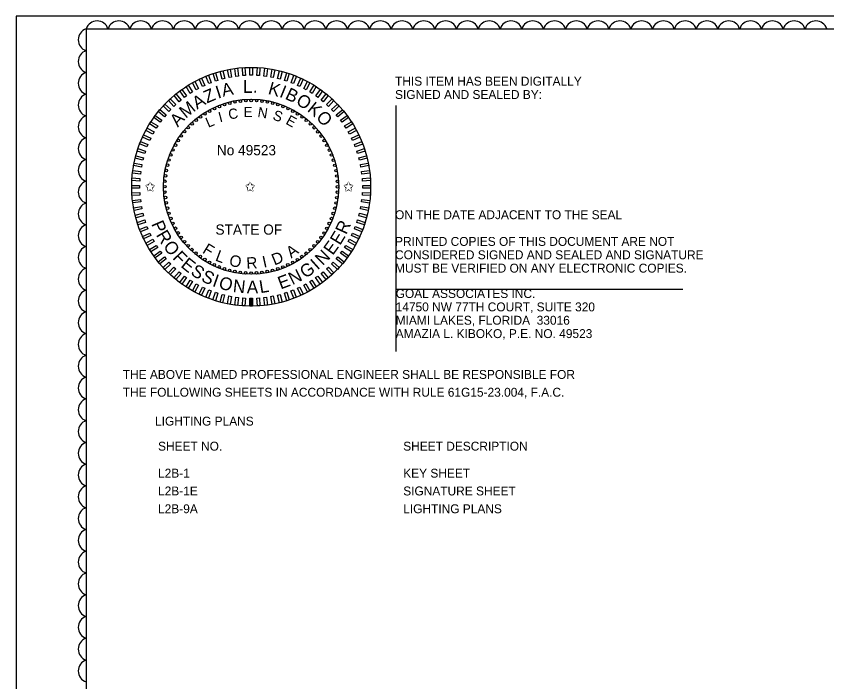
# Model space of a CAD drawing. Extents: x -816.9 to -790.1, y -2199.5 to -2188.9.
# Drawn here: x -811.34 to -804.97, y -2194.13 to -2188.9 of the extents above; entities that cross this region are included whole.
import ezdxf

# ---------------------------------------------------------------- set-up
doc = ezdxf.new("R2010")
doc.units = 0
for name, color, linetype in [('Cloud_dp', 7, 'Continuous'), ('Logo_dp', 7, 'Continuous'), ('NonPlottingEle_dp', 7, 'Continuous'), ('PlotBorder_dp', 7, 'Continuous'), ('ScratchEle_dp', 7, 'Continuous'), ('SheetBorder_dp', 7, 'Continuous'), ('TextMisc', 7, 'Continuous'), ('TextNotes', 7, 'Continuous')]:
    doc.layers.add(name, color=color, linetype=linetype)

msp = doc.modelspace()

# ---------------------------------------------------------------- linework, layer by layer
at = {"layer": 'Cloud_dp'}
for centre, start, end in [((-810.7002, -2189.0276), 17.5, 162.5), ((-810.5291, -2189.0276), 17.5, 162.5), ((-810.358, -2189.0276), 17.5, 162.5), ((-810.1868, -2189.0276), 17.5, 162.5), ((-810.0157, -2189.0276), 17.5, 162.5), ((-809.8446, -2189.0276), 17.5, 162.5), ((-809.6735, -2189.0276), 17.5, 162.5), ((-809.5024, -2189.0276), 17.5, 162.5), ((-809.3312, -2189.0276), 17.5, 162.5), ((-809.1601, -2189.0276), 17.5, 162.5), ((-808.989, -2189.0276), 17.5, 162.5), ((-808.8179, -2189.0276), 17.5, 162.5), ((-808.6467, -2189.0276), 17.5, 162.5), ((-808.4756, -2189.0276), 17.5, 162.5), ((-808.3045, -2189.0276), 17.5, 162.5), ((-808.1334, -2189.0276), 17.5, 162.5), ((-807.9622, -2189.0276), 17.5, 162.5), ((-807.7911, -2189.0276), 17.5, 162.5), ((-807.62, -2189.0276), 17.5, 162.5), ((-807.4489, -2189.0276), 17.5, 162.5), ((-807.2778, -2189.0276), 17.5, 162.5), ((-807.1066, -2189.0276), 17.5, 162.5), ((-806.9355, -2189.0276), 17.5, 162.5), ((-806.7644, -2189.0276), 17.5, 162.5), ((-806.5933, -2189.0276), 17.5, 162.5), ((-806.4221, -2189.0276), 17.5, 162.5), ((-806.251, -2189.0276), 17.5, 162.5), ((-806.0799, -2189.0276), 17.5, 162.5), ((-805.9088, -2189.0276), 17.5, 162.5), ((-805.7377, -2189.0276), 17.5, 162.5), ((-805.5665, -2189.0276), 17.5, 162.5), ((-805.3954, -2189.0276), 17.5, 162.5), ((-805.2243, -2189.0276), 17.5, 162.5), ((-805.0532, -2189.0276), 17.5, 162.5), ((-810.7588, -2189.0862), 107.5, 252.5), ((-810.7588, -2189.2573), 107.5, 252.5), ((-810.7588, -2189.4284), 107.5, 252.5), ((-810.7588, -2189.5996), 107.5, 252.5), ((-810.7588, -2189.7707), 107.5, 252.5), ((-810.7588, -2189.9418), 107.5, 252.5), ((-810.7588, -2190.1129), 107.5, 252.5), ((-810.7588, -2190.2841), 107.5, 252.5), ((-810.7588, -2190.4552), 107.5, 252.5), ((-810.7588, -2190.6263), 107.5, 252.5), ((-810.7588, -2190.7974), 107.5, 252.5), ((-810.7588, -2190.9685), 107.5, 252.5), ((-810.7588, -2191.1397), 107.5, 252.5), ((-810.7588, -2191.3108), 107.5, 252.5), ((-810.7588, -2191.4819), 107.5, 252.5), ((-810.7588, -2191.653), 107.5, 252.5), ((-810.7588, -2191.8242), 107.5, 252.5), ((-810.7588, -2191.9953), 107.5, 252.5), ((-810.7588, -2192.1664), 107.5, 252.5), ((-810.7588, -2192.3375), 107.5, 252.5), ((-810.7588, -2192.5087), 107.5, 252.5), ((-810.7588, -2192.6798), 107.5, 252.5), ((-810.7588, -2192.8509), 107.5, 252.5), ((-810.7588, -2193.022), 107.5, 252.5), ((-810.7588, -2193.1931), 107.5, 252.5), ((-810.7588, -2193.3643), 107.5, 252.5), ((-810.7588, -2193.5354), 107.5, 252.5), ((-810.7588, -2193.7065), 107.5, 252.5), ((-810.7588, -2193.8776), 107.5, 252.5), ((-810.7588, -2194.0488), 107.5, 252.5)]:
    msp.add_arc(centre, 0.0897, start, end, dxfattribs=at)
at = {"layer": 'Logo_dp'}
for p, q in [((-809.5, -2191.1804), (-809.5002, -2191.1179)), ((-809.49, -2191.1804), (-809.4902, -2191.1178)), ((-809.48, -2191.1804), (-809.4802, -2191.1178))]:
    msp.add_line(p, q, dxfattribs=at)
for points in [[(-809.5897, -2189.3711), (-809.6098, -2189.3737), (-809.6176, -2189.3116), (-809.5976, -2189.3091)], [(-809.5349, -2189.3666), (-809.555, -2189.3679), (-809.559, -2189.3055), (-809.5388, -2189.3042)], [(-809.4798, -2189.3655), (-809.5, -2189.3655), (-809.5, -2189.303), (-809.4798, -2189.303)], [(-809.4248, -2189.3679), (-809.445, -2189.3666), (-809.4411, -2189.3042), (-809.4209, -2189.3055)], [(-809.3701, -2189.3737), (-809.3901, -2189.3712), (-809.3823, -2189.3091), (-809.3623, -2189.3117)], [(-809.8031, -2189.4233), (-809.8219, -2189.4307), (-809.8449, -2189.3726), (-809.8261, -2189.3652)], [(-809.7511, -2189.4052), (-809.7703, -2189.4115), (-809.7896, -2189.352), (-809.7704, -2189.3458)], [(-809.698, -2189.3905), (-809.7176, -2189.3955), (-809.7332, -2189.335), (-809.7136, -2189.3299)], [(-809.6442, -2189.3791), (-809.664, -2189.3829), (-809.6758, -2189.3215), (-809.6559, -2189.3177)], [(-809.3158, -2189.3829), (-809.3357, -2189.3792), (-809.324, -2189.3177), (-809.3041, -2189.3215)], [(-809.2623, -2189.3956), (-809.2818, -2189.3905), (-809.2663, -2189.33), (-809.2467, -2189.335)], [(-809.2096, -2189.4115), (-809.2288, -2189.4053), (-809.2095, -2189.3458), (-809.1903, -2189.3521)], [(-809.158, -2189.4308), (-809.1768, -2189.4234), (-809.1538, -2189.3652), (-809.135, -2189.3727)], [(-809.9032, -2189.469), (-809.9209, -2189.4787), (-809.951, -2189.4239), (-809.9333, -2189.4142)], [(-809.8539, -2189.4446), (-809.8721, -2189.4532), (-809.8988, -2189.3966), (-809.8805, -2189.388)], [(-809.1077, -2189.4532), (-809.126, -2189.4446), (-809.0994, -2189.3881), (-809.0811, -2189.3967)], [(-809.059, -2189.4788), (-809.0767, -2189.4691), (-809.0466, -2189.4143), (-809.0289, -2189.424)], [(-809.9968, -2189.5268), (-810.0131, -2189.5387), (-810.0499, -2189.4881), (-810.0335, -2189.4763)], [(-809.9509, -2189.4964), (-809.968, -2189.5073), (-810.0015, -2189.4545), (-809.9844, -2189.4437)], [(-809.0119, -2189.5074), (-809.029, -2189.4965), (-808.9955, -2189.4438), (-808.9784, -2189.4546)], [(-808.9668, -2189.5388), (-808.9831, -2189.527), (-808.9464, -2189.4764), (-808.93, -2189.4883)], [(-810.0824, -2189.596), (-810.0971, -2189.6098), (-810.1399, -2189.5643), (-810.1252, -2189.5504)], [(-810.0407, -2189.5601), (-810.0562, -2189.573), (-810.0961, -2189.5248), (-810.0805, -2189.5119)], [(-808.9237, -2189.5731), (-808.9392, -2189.5602), (-808.8994, -2189.512), (-808.8838, -2189.5249)], [(-808.8828, -2189.61), (-808.8975, -2189.5961), (-808.8547, -2189.5505), (-808.84, -2189.5644)], [(-810.1217, -2189.6345), (-810.1356, -2189.6492), (-810.1812, -2189.6064), (-810.1673, -2189.5917)], [(-808.8443, -2189.6493), (-808.8582, -2189.6346), (-808.8126, -2189.5918), (-808.7988, -2189.6065)], [(-810.1929, -2189.7184), (-810.2048, -2189.7348), (-810.2553, -2189.698), (-810.2435, -2189.6817)], [(-810.1586, -2189.6753), (-810.1715, -2189.6909), (-810.2197, -2189.6511), (-810.2068, -2189.6355)], [(-808.8084, -2189.691), (-808.8213, -2189.6755), (-808.7731, -2189.6356), (-808.7602, -2189.6512)], [(-808.7752, -2189.7349), (-808.7871, -2189.7186), (-808.7365, -2189.6818), (-808.7246, -2189.6982)], [(-810.2243, -2189.7636), (-810.2352, -2189.7807), (-810.288, -2189.7472), (-810.2771, -2189.7301)], [(-808.7448, -2189.7808), (-808.7556, -2189.7638), (-808.7028, -2189.7303), (-808.692, -2189.7473)], [(-810.2529, -2189.8106), (-810.2626, -2189.8284), (-810.3174, -2189.7982), (-810.3077, -2189.7805)], [(-808.7173, -2189.8285), (-808.7271, -2189.8108), (-808.6723, -2189.7807), (-808.6625, -2189.7984)], [(-810.2785, -2189.8594), (-810.2871, -2189.8777), (-810.3436, -2189.8511), (-810.335, -2189.8328)], [(-808.6929, -2189.8779), (-808.7015, -2189.8596), (-808.6449, -2189.8329), (-808.6363, -2189.8512)], [(-810.3202, -2189.9612), (-810.3264, -2189.9805), (-810.3859, -2189.9611), (-810.3796, -2189.9419)], [(-810.3009, -2189.9097), (-810.3084, -2189.9285), (-810.3665, -2189.9054), (-810.359, -2189.8866)], [(-808.6716, -2189.9286), (-808.6791, -2189.9098), (-808.6209, -2189.8868), (-808.6135, -2189.9056)], [(-808.6536, -2189.9806), (-808.6598, -2189.9614), (-808.6004, -2189.9421), (-808.5941, -2189.9613)], [(-810.3361, -2190.0139), (-810.3412, -2190.0335), (-810.4017, -2190.0179), (-810.3967, -2189.9984)], [(-808.6388, -2190.0337), (-808.6439, -2190.0141), (-808.5833, -2189.9985), (-808.5783, -2190.0181)], [(-810.3488, -2190.0675), (-810.3526, -2190.0873), (-810.414, -2190.0756), (-810.4102, -2190.0558)], [(-808.6275, -2190.0875), (-808.6312, -2190.0677), (-808.5698, -2190.056), (-808.566, -2190.0758)], [(-810.358, -2190.1218), (-810.3605, -2190.1418), (-810.4226, -2190.134), (-810.42, -2190.1139)], [(-808.6195, -2190.142), (-808.622, -2190.1219), (-808.56, -2190.1141), (-808.5575, -2190.1342)], [(-810.3638, -2190.1765), (-810.3651, -2190.1967), (-810.4275, -2190.1927), (-810.4262, -2190.1726)], [(-808.6149, -2190.1968), (-808.6162, -2190.1767), (-808.5538, -2190.1727), (-808.5525, -2190.1929)], [(-810.3662, -2190.2315), (-810.3662, -2190.2517), (-810.4287, -2190.2517), (-810.4287, -2190.2315)], [(-808.6139, -2190.2519), (-808.6139, -2190.2317), (-808.5513, -2190.2317), (-808.5513, -2190.2519)], [(-810.3651, -2190.2865), (-810.3638, -2190.3067), (-810.4262, -2190.3106), (-810.4275, -2190.2904)], [(-808.6162, -2190.3069), (-808.615, -2190.2867), (-808.5526, -2190.2906), (-808.5538, -2190.3108)], [(-810.3606, -2190.3414), (-810.358, -2190.3614), (-810.4201, -2190.3693), (-810.4226, -2190.3492)], [(-808.622, -2190.3616), (-808.6195, -2190.3416), (-808.5575, -2190.3494), (-808.56, -2190.3695)], [(-810.3526, -2190.3958), (-810.3488, -2190.4157), (-810.4102, -2190.4274), (-810.414, -2190.4076)], [(-810.3412, -2190.4497), (-810.3362, -2190.4693), (-810.3967, -2190.4848), (-810.4018, -2190.4652)], [(-808.6439, -2190.4695), (-808.6389, -2190.4499), (-808.5783, -2190.4654), (-808.5834, -2190.485)], [(-808.6313, -2190.4159), (-808.6275, -2190.396), (-808.5661, -2190.4077), (-808.5699, -2190.4276)], [(-810.3265, -2190.5027), (-810.3202, -2190.522), (-810.3797, -2190.5413), (-810.3859, -2190.5221)], [(-808.6599, -2190.5221), (-808.6536, -2190.5029), (-808.5942, -2190.5222), (-808.6004, -2190.5415)], [(-810.3084, -2190.5547), (-810.301, -2190.5735), (-810.3591, -2190.5966), (-810.3666, -2190.5778)], [(-808.6791, -2190.5737), (-808.6717, -2190.5549), (-808.6136, -2190.5779), (-808.621, -2190.5967)], [(-810.2872, -2190.6055), (-810.2785, -2190.6238), (-810.3351, -2190.6504), (-810.3437, -2190.6321)], [(-808.7016, -2190.624), (-808.693, -2190.6057), (-808.6364, -2190.6323), (-808.645, -2190.6506)], [(-810.2627, -2190.6548), (-810.253, -2190.6726), (-810.3078, -2190.7027), (-810.3175, -2190.685)], [(-810.2353, -2190.7026), (-810.2244, -2190.7196), (-810.2772, -2190.7531), (-810.2881, -2190.7361)], [(-808.7557, -2190.7198), (-808.7449, -2190.7027), (-808.6921, -2190.7362), (-808.7029, -2190.7533)], [(-808.7271, -2190.6727), (-808.7174, -2190.655), (-808.6626, -2190.6851), (-808.6724, -2190.7028)], [(-810.2049, -2190.7484), (-810.193, -2190.7648), (-810.2436, -2190.8015), (-810.2554, -2190.7852)], [(-808.7872, -2190.7649), (-808.7753, -2190.7486), (-808.7247, -2190.7853), (-808.7366, -2190.8017)], [(-810.1716, -2190.7923), (-810.1587, -2190.8079), (-810.2069, -2190.8477), (-810.2198, -2190.8322)], [(-810.1357, -2190.834), (-810.1219, -2190.8488), (-810.1675, -2190.8916), (-810.1813, -2190.8768)], [(-808.8583, -2190.8489), (-808.8445, -2190.8342), (-808.7989, -2190.877), (-808.8127, -2190.8917)], [(-808.8214, -2190.808), (-808.8085, -2190.7925), (-808.7604, -2190.8323), (-808.7732, -2190.8479)], [(-810.0972, -2190.8734), (-810.0825, -2190.8872), (-810.1253, -2190.9328), (-810.14, -2190.919)], [(-808.8977, -2190.8874), (-808.8829, -2190.8735), (-808.8401, -2190.9191), (-808.8549, -2190.9329)], [(-810.0564, -2190.9103), (-810.0408, -2190.9232), (-810.0807, -2190.9713), (-810.0962, -2190.9585)], [(-810.0133, -2190.9445), (-809.9969, -2190.9564), (-810.0337, -2191.007), (-810.05, -2190.9951)], [(-808.9833, -2190.9565), (-808.9669, -2190.9446), (-808.9302, -2190.9952), (-808.9465, -2191.0071)], [(-808.9394, -2190.9233), (-808.9238, -2190.9104), (-808.884, -2190.9586), (-808.8995, -2190.9715)], [(-809.9681, -2190.976), (-809.951, -2190.9868), (-809.9845, -2191.0396), (-810.0016, -2191.0288)], [(-809.9211, -2191.0046), (-809.9034, -2191.0143), (-809.9335, -2191.0691), (-809.9512, -2191.0594)], [(-809.8723, -2191.0301), (-809.854, -2191.0387), (-809.8806, -2191.0953), (-809.8989, -2191.0867)], [(-809.1262, -2191.0388), (-809.1079, -2191.0302), (-809.0813, -2191.0868), (-809.0996, -2191.0954)], [(-809.0769, -2191.0144), (-809.0592, -2191.0047), (-809.029, -2191.0594), (-809.0467, -2191.0692)], [(-809.0292, -2190.9869), (-809.0121, -2190.9761), (-808.9786, -2191.0289), (-808.9957, -2191.0397)], [(-809.822, -2191.0526), (-809.8033, -2191.06), (-809.8263, -2191.1181), (-809.8451, -2191.1107)], [(-809.7705, -2191.0718), (-809.7513, -2191.0781), (-809.7706, -2191.1375), (-809.7898, -2191.1313)], [(-809.7178, -2191.0878), (-809.6982, -2191.0928), (-809.7138, -2191.1534), (-809.7333, -2191.1484)], [(-809.282, -2191.0929), (-809.2624, -2191.0878), (-809.2469, -2191.1484), (-809.2665, -2191.1534)], [(-809.229, -2191.0781), (-809.2097, -2191.0719), (-809.1904, -2191.1313), (-809.2097, -2191.1376)], [(-809.177, -2191.0601), (-809.1582, -2191.0526), (-809.1352, -2191.1108), (-809.154, -2191.1182)], [(-809.6642, -2191.1004), (-809.6444, -2191.1042), (-809.6561, -2191.1656), (-809.6759, -2191.1618)], [(-809.61, -2191.1097), (-809.5899, -2191.1122), (-809.5977, -2191.1742), (-809.6178, -2191.1717)], [(-809.5552, -2191.1155), (-809.535, -2191.1168), (-809.539, -2191.1792), (-809.5591, -2191.1779)], [(-809.5002, -2191.1179), (-809.48, -2191.1179), (-809.48, -2191.1804), (-809.5002, -2191.1804)], [(-809.4452, -2191.1168), (-809.425, -2191.1155), (-809.4211, -2191.1779), (-809.4413, -2191.1792)], [(-809.3903, -2191.1122), (-809.3703, -2191.1097), (-809.3624, -2191.1717), (-809.3825, -2191.1743)], [(-809.3359, -2191.1043), (-809.316, -2191.1005), (-809.3043, -2191.1619), (-809.3241, -2191.1657)]]:
    msp.add_lwpolyline(points, close=True, dxfattribs=at)
for centre in [(-809.6166, -2189.5752), (-809.5745, -2189.5686), (-809.5321, -2189.5646), (-809.4895, -2189.5633), (-809.4469, -2189.5647), (-809.4044, -2189.5687), (-809.3624, -2189.5755), (-809.7783, -2189.6277), (-809.7392, -2189.6108), (-809.6991, -2189.5964), (-809.6582, -2189.5845), (-809.3208, -2189.5848), (-809.2799, -2189.5967), (-809.2398, -2189.6112), (-809.2007, -2189.6281), (-809.8883, -2189.6926), (-809.853, -2189.6686), (-809.8163, -2189.647), (-809.1627, -2189.6475), (-809.1261, -2189.6692), (-809.0908, -2189.6932), (-809.954, -2189.7468), (-809.922, -2189.7186), (-809.0572, -2189.7194), (-809.0252, -2189.7476), (-810.0123, -2189.8088), (-809.9841, -2189.7769), (-808.9951, -2189.7777), (-808.967, -2189.8097), (-810.0625, -2189.8777), (-810.0385, -2189.8425), (-808.9409, -2189.8434), (-808.917, -2189.8787), (-810.1036, -2189.9523), (-810.0842, -2189.9144), (-808.8953, -2189.9154), (-808.876, -2189.9534), (-810.1205, -2189.9914), (-808.8591, -2189.9925), (-810.1469, -2190.0724), (-810.135, -2190.0315), (-808.8447, -2190.0326), (-808.8328, -2190.0735), (-810.1563, -2190.114), (-808.8236, -2190.1151), (-810.167, -2190.1985), (-810.163, -2190.1561), (-808.8169, -2190.1572), (-808.813, -2190.1997), (-810.1684, -2190.2411), (-808.8117, -2190.2422), (-810.1671, -2190.2837), (-810.1631, -2190.3261), (-808.8171, -2190.3273), (-808.813, -2190.2848), (-810.1565, -2190.3682), (-808.8238, -2190.3693), (-810.1472, -2190.4098), (-810.1354, -2190.4508), (-808.845, -2190.4518), (-808.8331, -2190.4109), (-810.121, -2190.4909), (-810.1041, -2190.53), (-808.8595, -2190.4919), (-810.0847, -2190.568), (-808.8959, -2190.569), (-808.8765, -2190.531), (-810.0631, -2190.6047), (-810.0392, -2190.64), (-808.9416, -2190.6409), (-808.9176, -2190.6056), (-810.0131, -2190.6736), (-809.9849, -2190.7056), (-808.9959, -2190.7065), (-808.9677, -2190.6745), (-809.9548, -2190.7358), (-809.9229, -2190.764), (-809.0581, -2190.7647), (-809.0261, -2190.7366), (-809.8892, -2190.7902), (-809.854, -2190.8141), (-809.8173, -2190.8359), (-809.1637, -2190.8364), (-809.127, -2190.8147), (-809.0918, -2190.7908), (-809.7794, -2190.8552), (-809.7403, -2190.8722), (-809.7002, -2190.8867), (-809.6593, -2190.8986), (-809.6177, -2190.9079), (-809.3635, -2190.9081), (-809.3219, -2190.8989), (-809.2809, -2190.887), (-809.2408, -2190.8726), (-809.2017, -2190.8557), (-809.5756, -2190.9146), (-809.5332, -2190.9187), (-809.49, -2190.9201), (-809.448, -2190.9187), (-809.4056, -2190.9148)]:
    msp.add_circle(centre, 0.01, dxfattribs=at)
at = {"layer": 'NonPlottingEle_dp'}
for radius in [0.9387, 0.6884]:
    msp.add_circle((-809.49, -2190.2417), radius, dxfattribs=at)
at = {"layer": 'PlotBorder_dp'}
msp.add_lwpolyline([(-811.3358, -2199.5006), (-794.8358, -2199.5006), (-794.8358, -2188.9006), (-811.3358, -2188.9006)], close=True, dxfattribs=at)
at = {"layer": 'ScratchEle_dp'}
for p, q in [((-808.3546, -2189.6017), (-808.3546, -2191.5365)), ((-808.3546, -2191.0465), (-806.0979, -2191.0465))]:
    msp.add_line(p, q, dxfattribs=at)
at = {"layer": 'SheetBorder_dp'}
for q in [(-810.7858, -2199.4006), (-795.3858, -2189.0006)]:
    msp.add_line((-810.7858, -2189.0006), q, dxfattribs=at)

# ---------------------------------------------------------------- texts
at = {"layer": 'Logo_dp'}
for s, rotation, p in [('C', 8.98261, (-809.6632, -2189.7131)), ('E', 359.96623, (-809.5504, -2189.6942)), ('N', 350.64643, (-809.4434, -2189.6927)), ('I', 14.81888, (-809.7359, -2189.7358)), ('S', 341.03996, (-809.3261, -2189.7116)), ('E', 331.16864, (-809.2245, -2189.7442)), ('L', 23.30524, (-809.8266, -2189.7788))]:
    msp.add_text(s, height=0.0801, rotation=rotation, dxfattribs=at).set_placement(p)
for p in [(-810.3261, -2190.2797), (-809.5404, -2190.2797), (-808.7675, -2190.2797)]:
    msp.add_text('✩', height=0.0801, dxfattribs=at).set_placement(p)
at = {"layer": 'TextMisc'}
for s, height, rotation, p in [('A', 0.1001, 11.91844, (-809.7111, -2189.5338)), ('L', 0.1001, 359.96623, (-809.5537, -2189.5034)), ('K', 0.1001, 344.27273, (-809.3628, -2189.5106)), ('Z', 0.1001, 23.30524, (-809.8374, -2189.5875)), ('I', 0.1001, 17.68363, (-809.7505, -2189.5498)), ('.', 0.1001, 353.78581, (-809.4769, -2189.5005)), ('I', 0.1001, 337.77772, (-809.2741, -2189.5325)), ('B', 0.1001, 334.48695, (-809.23, -2189.5478)), ('A', 0.1001, 31.46601, (-809.9149, -2189.6362)), ('O', 0.1001, 327.82385, (-809.1453, -2189.5865)), ('M', 0.1001, 39.30005, (-810.0041, -2189.7084)), ('K', 0.1001, 321.0594, (-809.0556, -2189.6437)), ('A', 0.1001, 46.80938, (-810.0664, -2189.777)), ('O', 0.1001, 314.20329, (-808.9858, -2189.7014)), ('P', 0.1002, 293.19548, (-810.2767, -2190.5336)), ('R', 0.1002, 65.28865, (-808.7427, -2190.6231)), ('R', 0.1002, 300.25949, (-810.2398, -2190.6197)), ('E', 0.1002, 58.61694, (-808.7919, -2190.7072)), ('O', 0.1002, 307.26617, (-810.1856, -2190.7116)), ('F', 0.0902, 328.53399, (-809.879, -2190.7577)), ('A', 0.0902, 35.54629, (-809.1752, -2190.807)), ('E', 0.1002, 53.99864, (-808.8492, -2190.786)), ('F', 0.1002, 314.20329, (-810.1121, -2190.8042)), ('L', 0.0902, 339.48752, (-809.7776, -2190.8207)), ('D', 0.0902, 22.22228, (-809.3071, -2190.8616)), ('N', 0.1002, 44.34211, (-808.9294, -2190.866)), ('E', 0.1002, 321.0594, (-810.0487, -2190.8679)), ('O', 0.0902, 348.08156, (-809.668, -2190.8614)), ('R', 0.0902, 3.10738, (-809.5257, -2190.8876)), ('I', 0.0902, 12.52485, (-809.3913, -2190.8785)), ('I', 0.1002, 41.83906, (-808.9688, -2190.9003)), ('S', 0.1002, 327.82385, (-809.9723, -2190.9285)), ('S', 0.1002, 334.48695, (-809.8891, -2190.98)), ('N', 0.1002, 26.0618, (-809.1664, -2191.0166)), ('G', 0.1002, 34.11362, (-809.0651, -2190.9664)), ('I', 0.1002, 341.03996, (-809.8004, -2191.0213)), ('O', 0.1002, 344.27273, (-809.7512, -2191.0389)), ('E', 0.1002, 20.51248, (-809.2581, -2191.0499)), ('N', 0.1002, 353.78581, (-809.6367, -2191.0689)), ('A', 0.1002, 359.96623, (-809.5242, -2191.0799)), ('L', 0.1002, 8.98261, (-809.4185, -2191.079))]:
    msp.add_text(s, height=height, rotation=rotation, dxfattribs=at).set_placement(p)
for s, height, p in [('THIS ITEM HAS BEEN DIGITALLY', 0.07, (-808.3596, -2189.4466)), ('SIGNED AND SEALED BY:', 0.07, (-808.3596, -2189.5516)), ('No 49523', 0.0801, (-809.7593, -2189.9941)), ('ON THE DATE ADJACENT TO THE SEAL', 0.07, (-808.3596, -2190.4966)), ('STATE OF', 0.0801, (-809.7701, -2190.6184)), ('PRINTED COPIES OF THIS DOCUMENT ARE NOT ', 0.07, (-808.3596, -2190.7066)), ('CONSIDERED SIGNED AND SEALED AND SIGNATURE ', 0.07, (-808.3596, -2190.8116)), ('MUST BE VERIFIED ON ANY ELECTRONIC COPIES.', 0.07, (-808.3596, -2190.9166)), ('GOAL ASSOCIATES INC.', 0.07, (-808.3546, -2191.1165)), ('14750 NW 77TH COURT, SUITE 320', 0.07, (-808.3546, -2191.2215)), ('MIAMI LAKES, FLORIDA  33016', 0.07, (-808.3546, -2191.3265)), ('AMAZIA L. KIBOKO, P.E. NO. 49523', 0.07, (-808.3546, -2191.4315)), ('THE ABOVE NAMED PROFESSIONAL ENGINEER SHALL BE RESPONSIBLE FOR ', 0.07, (-810.4987, -2191.7526)), ('THE FOLLOWING SHEETS IN ACCORDANCE WITH RULE 61G15-23.004, F.A.C.', 0.07, (-810.4987, -2191.8926)), ('LIGHTING PLANS', 0.07, (-810.245, -2192.1196))]:
    msp.add_text(s, height=height, dxfattribs=at).set_placement(p)
at = {"layer": 'TextNotes'}
for s, p in [('SHEET NO.', (-810.2215, -2192.3166)), ('SHEET DESCRIPTION', (-808.2953, -2192.3166)), ('L2B-1', (-810.2215, -2192.5288)), ('KEY SHEET', (-808.2953, -2192.5288)), ('L2B-1E', (-810.2215, -2192.6688)), ('SIGNATURE SHEET', (-808.2953, -2192.6688)), ('L2B-9A', (-810.2215, -2192.8088)), ('LIGHTING PLANS', (-808.2953, -2192.8088))]:
    msp.add_text(s, height=0.07, dxfattribs=at).set_placement(p)

doc.saveas('drawing.dxf')
